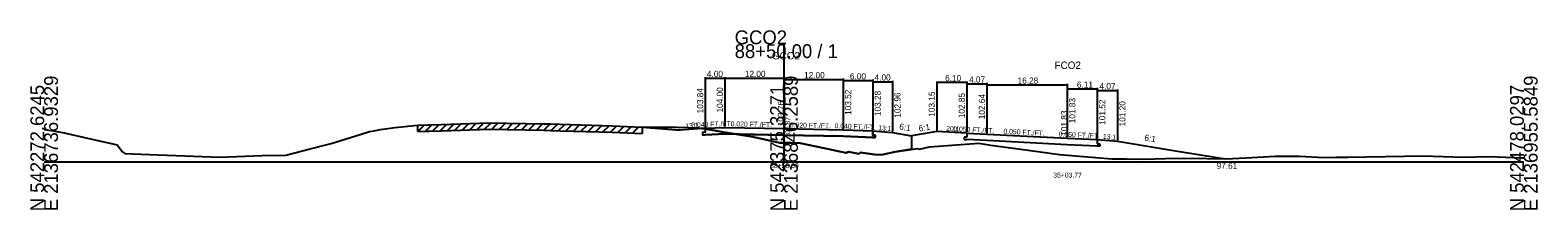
# Model space of a CAD drawing. Extents: x -14327 to 8886, y -10 to 39048.
# Drawn here: x 2997.2 to 3302.8, y 36990.3 to 37026.7 of the extents above; entities that cross this region are included whole.
import ezdxf

# ---------------------------------------------------------------- set-up
doc = ezdxf.new("R2010")
doc.units = 0
for name, color, linetype in [('Level 20', 7, 'Continuous'), ('Level 5', 7, 'Continuous'), ('Level 53', 7, 'Continuous'), ('Level 54', 7, 'Continuous'), ('Level 55', 7, 'Continuous'), ('Level 7', 7, 'Continuous'), ('RD_GPK_XS_Cell', 7, 'Continuous'), ('RD_XS_EwShp', 7, 'Continuous'), ('RD_XS_ExGround', 7, 'Continuous'), ('RD_XS_ExPaveRet', 7, 'Continuous'), ('RD_XS_Pave', 7, 'Continuous'), ('RD_XS_TX_Baseline', 7, 'Continuous'), ('RD_XS_TX_Elev_EX', 7, 'Continuous'), ('RD_XS_TX_Elev_PR', 7, 'Continuous'), ('RD_XS_TX_Station', 7, 'Continuous')]:
    doc.layers.add(name, color=color, linetype=linetype)

msp = doc.modelspace()

# ---------------------------------------------------------------- linework, layer by layer
at = {"layer": 'Level 20'}
for p, q in [((3180.96, 37016.3), (3180.96, 37006.35)), ((3187.06, 37016.1), (3180.96, 37016.1)), ((3187.06, 37016.3), (3187.06, 37006.05)), ((3187.06, 37016), (3187.06, 37006.05)), ((3187.06, 37015.8), (3191.13, 37015.8)), ((3191.13, 37016), (3191.13, 37005.84)), ((3191.13, 37015.79), (3191.13, 37005.84)), ((3191.13, 37015.59), (3207.41, 37015.59)), ((3207.41, 37015.79), (3207.41, 37005.03)), ((3207.41, 37014.98), (3207.41, 37005.03)), ((3213.52, 37014.98), (3213.52, 37004.72)), ((3207.41, 37014.78), (3213.52, 37014.78)), ((3213.52, 37014.67), (3213.52, 37004.72)), ((3213.52, 37014.47), (3217.59, 37014.47)), ((3217.59, 37014.67), (3217.59, 37004.4)), ((3180.96, 37006.15), (3175.88, 37005.31)), ((3187.06, 37005.85), (3180.96, 37006.15)), ((3187.06, 37005.85), (3187.06, 37005.01)), ((3187.06, 37005.85), (3191.13, 37005.64)), ((3186.56, 37005.04), (3186.56, 37004.54)), ((3187.06, 37005.01), (3186.56, 37005.04)), ((3186.56, 37004.54), (3187.06, 37004.51)), ((3191.13, 37004.31), (3187.06, 37004.51)), ((3191.13, 37005.64), (3207.41, 37004.83)), ((3207.41, 37003.49), (3191.13, 37004.31)), ((3207.41, 37004.83), (3213.52, 37004.52)), ((3213.52, 37003.19), (3207.41, 37003.49)), ((3213.52, 37004.52), (3213.52, 37003.69)), ((3213.52, 37004.52), (3217.59, 37004.2)), ((3213.52, 37003.69), (3214.03, 37003.66)), ((3214.03, 37003.16), (3213.52, 37003.19)), ((3214.03, 37003.66), (3214.03, 37003.16)), ((3217.59, 37004.2), (3229.8, 37002.2)), ((3229.8, 37002.2), (3239.52, 37000.61))]:
    msp.add_line(p, q, dxfattribs=at)
at = {"layer": 'Level 5'}
for p, q in [((3134, 37006.01), (3133.5, 37005.99)), ((3133.5, 37005.99), (3133.5, 37005.49)), ((3134, 37006.84), (3134, 37006.01)), ((3168, 37006.28), (3168, 37005.45)), ((3133.5, 37005.49), (3134, 37005.51)), ((3138, 37005.67), (3134, 37005.51)), ((3150, 37005.43), (3138, 37005.67)), ((3162, 37005.19), (3150, 37005.43)), ((3168, 37004.95), (3162, 37005.19)), ((3168, 37005.45), (3168.5, 37005.43)), ((3168.5, 37004.93), (3168, 37004.95)), ((3168.5, 37005.43), (3168.5, 37004.93))]:
    msp.add_line(p, q, dxfattribs=at)
at = {"layer": 'Level 54'}
for p, q in [((3134, 37017.15), (3134, 37007.04)), ((3134, 37016.99), (3134, 37007.04)), ((3134, 37016.95), (3138, 37016.95)), ((3138, 37017.15), (3138, 37007.2)), ((3138, 37016.95), (3150, 37016.95)), ((3150, 37017.15), (3150, 37006.96)), ((3150, 37016.91), (3150, 37006.96)), ((3150, 37016.71), (3162, 37016.71)), ((3162, 37016.91), (3162, 37006.72)), ((3162, 37016.67), (3162, 37006.72)), ((3162, 37016.47), (3168, 37016.47)), ((3168, 37016.67), (3168, 37006.48)), ((3168, 37016.43), (3168, 37006.48)), ((3168, 37016.23), (3172, 37016.23)), ((3172, 37016.43), (3172, 37006.16))]:
    msp.add_line(p, q, dxfattribs=at)
at = {"layer": 'Level 7'}
for p, q in [((3121.23, 37007.06), (3128.98, 37006.44)), ((3134, 37006.84), (3128.98, 37006.44)), ((3168, 37006.28), (3172, 37005.96)), ((3172, 37005.96), (3175.88, 37005.31)), ((3175.88, 37005.31), (3175.88, 37002.56))]:
    msp.add_line(p, q, dxfattribs=at)
at = {"layer": 'RD_GPK_XS_Cell'}
for p, q in [((3150, 37000), (3150, 37023.83)), ((3000, 37000), (3150, 37000)), ((3150, 37000), (3300, 37000))]:
    msp.add_line(p, q, dxfattribs=at)
at = {"layer": 'RD_XS_EwShp'}
for points in [[(3130.54, 37006.97), (3133.25, 37006.81), (3133.39, 37006.79), (3128.98, 37006.44), (3121.23, 37007.06), (3126.19, 37007.12)], [(3133.39, 37006.79), (3134, 37006.69), (3134, 37006.84)], [(3134, 37006.69), (3134, 37006.01), (3133.5, 37005.99), (3133.5, 37005.49), (3134, 37005.51), (3138, 37005.67), (3140.36, 37005.62), (3138.12, 37005.98)], [(3175.88, 37005.31), (3175.88, 37002.56), (3172.56, 37002.07), (3169.77, 37001.47), (3168.38, 37001.5), (3165.49, 37001.91), (3165.15, 37001.64), (3163.12, 37002.03), (3162.52, 37001.82), (3157.79, 37002.84), (3153.26, 37003.79), (3151.33, 37003.86), (3150, 37003.87), (3149.12, 37003.88), (3146.1, 37004.54), (3143.26, 37005.15), (3140.36, 37005.62), (3150, 37005.43), (3162, 37005.19), (3168, 37004.95), (3168.5, 37004.93), (3168.5, 37005.43), (3168, 37005.45), (3168, 37006.28), (3172, 37005.96)]]:
    msp.add_lwpolyline(points, close=True, dxfattribs=at)
at = {"layer": 'RD_XS_ExGround'}
for p, q in [((3000, 37006.54), (3001.82, 37006.33)), ((3001.82, 37006.33), (3004.04, 37005.92)), ((3004.04, 37005.92), (3010.3, 37004.5)), ((3063.18, 37005.28), (3065.99, 37006.14)), ((3065.99, 37006.14), (3066.82, 37006.29)), ((3066.82, 37006.29), (3068.18, 37006.59)), ((3068.18, 37006.59), (3071.11, 37006.98)), ((3071.11, 37006.98), (3075.76, 37007.45)), ((3075.76, 37007.45), (3077.77, 37007.51)), ((3077.77, 37007.51), (3078.08, 37007.52)), ((3078.08, 37007.52), (3080.51, 37007.6)), ((3080.51, 37007.6), (3090.22, 37007.94)), ((3090.22, 37007.94), (3101.27, 37007.72)), ((3101.27, 37007.72), (3102.64, 37007.69)), ((3102.64, 37007.69), (3104.64, 37007.63)), ((3104.64, 37007.63), (3115.19, 37007.31)), ((3115.19, 37007.31), (3121.23, 37007.06)), ((3121.23, 37007.06), (3126.19, 37007.12)), ((3126.19, 37007.12), (3130.54, 37006.97)), ((3130.54, 37006.97), (3133.25, 37006.81)), ((3133.25, 37006.81), (3138.12, 37005.98)), ((3138.12, 37005.98), (3143.26, 37005.15)), ((3010.3, 37004.5), (3014.83, 37003.45)), ((3014.83, 37003.45), (3015.85, 37002.04)), ((3053.68, 37002.59), (3058.16, 37003.74)), ((3058.16, 37003.74), (3063.18, 37005.28)), ((3143.26, 37005.15), (3146.1, 37004.54)), ((3146.1, 37004.54), (3149.12, 37003.88)), ((3149.12, 37003.88), (3150, 37003.87)), ((3150, 37003.87), (3151.33, 37003.86)), ((3151.33, 37003.86), (3153.26, 37003.79)), ((3153.26, 37003.79), (3157.79, 37002.84)), ((3157.79, 37002.84), (3162.52, 37001.82)), ((3172.56, 37002.07), (3177.15, 37002.75)), ((3177.15, 37002.75), (3177.49, 37002.57)), ((3177.49, 37002.57), (3179.47, 37003.07)), ((3179.47, 37003.07), (3181.35, 37003.21)), ((3181.35, 37003.21), (3189.48, 37003.82)), ((3189.48, 37003.82), (3191.95, 37003.42)), ((3191.95, 37003.42), (3199.49, 37002.4)), ((3015.85, 37002.04), (3016.34, 37001.71)), ((3016.34, 37001.71), (3019.63, 37001.57)), ((3019.63, 37001.57), (3035.59, 37000.95)), ((3035.59, 37000.95), (3044.2, 37001.31)), ((3044.2, 37001.31), (3049.03, 37001.38)), ((3049.03, 37001.38), (3053.68, 37002.59)), ((3162.52, 37001.82), (3163.12, 37002.03)), ((3163.12, 37002.03), (3165.15, 37001.64)), ((3165.15, 37001.64), (3165.49, 37001.91)), ((3165.49, 37001.91), (3168.38, 37001.5)), ((3168.38, 37001.5), (3169.77, 37001.47)), ((3169.77, 37001.47), (3172.56, 37002.07)), ((3199.49, 37002.4), (3205.83, 37001.48)), ((3205.83, 37001.48), (3216.44, 37000.62)), ((3216.44, 37000.62), (3219.51, 37000.64)), ((3219.51, 37000.64), (3222.97, 37000.56)), ((3222.97, 37000.56), (3229.52, 37000.76)), ((3229.52, 37000.76), (3235.81, 37000.71)), ((3235.81, 37000.71), (3239.53, 37000.61)), ((3239.53, 37000.61), (3243.67, 37000.8)), ((3243.67, 37000.8), (3249.54, 37001.14)), ((3249.54, 37001.14), (3254.43, 37001.17)), ((3254.43, 37001.17), (3259.55, 37000.91)), ((3259.55, 37000.91), (3262.01, 37000.96)), ((3262.01, 37000.96), (3264.4, 37000.99)), ((3264.4, 37000.99), (3279.57, 37001.25)), ((3279.57, 37001.25), (3287.77, 37000.96)), ((3287.77, 37000.96), (3292.98, 37001.08)), ((3292.98, 37001.08), (3299.58, 37000.86)), ((3299.58, 37000.86), (3300, 37000.85))]:
    msp.add_line(p, q, dxfattribs=at)
at = {"layer": 'RD_XS_ExPaveRet'}
for p, q in [((3075.76, 37006.15), (3077.1, 37007.49)), ((3075.76, 37006.15), (3075.76, 37007.45)), ((3075.76, 37006.15), (3077.77, 37006.21)), ((3077.26, 37006.19), (3078.61, 37007.54)), ((3077.77, 37006.21), (3078.08, 37006.22)), ((3078.08, 37006.22), (3080.51, 37006.3)), ((3078.76, 37006.24), (3080.11, 37007.59)), ((3080.26, 37006.29), (3081.61, 37007.64)), ((3080.51, 37006.3), (3090.22, 37006.64)), ((3081.77, 37006.35), (3083.11, 37007.69)), ((3083.27, 37006.4), (3084.62, 37007.75)), ((3084.77, 37006.45), (3086.12, 37007.8)), ((3086.27, 37006.51), (3087.62, 37007.85)), ((3087.77, 37006.56), (3089.12, 37007.91)), ((3089.27, 37006.61), (3090.6, 37007.94)), ((3090.22, 37006.64), (3101.27, 37006.42)), ((3090.78, 37006.63), (3092.05, 37007.91)), ((3092.28, 37006.6), (3093.55, 37007.88)), ((3093.78, 37006.57), (3095.05, 37007.84)), ((3095.28, 37006.54), (3096.56, 37007.81)), ((3096.78, 37006.51), (3098.06, 37007.78)), ((3098.29, 37006.48), (3099.56, 37007.75)), ((3099.79, 37006.45), (3101.06, 37007.72)), ((3101.27, 37006.42), (3102.64, 37006.39)), ((3101.29, 37006.41), (3102.57, 37007.69)), ((3102.64, 37006.39), (3104.64, 37006.33)), ((3102.79, 37006.38), (3104.05, 37007.64)), ((3104.29, 37006.34), (3105.56, 37007.6)), ((3104.64, 37006.33), (3115.19, 37006.01)), ((3105.79, 37006.29), (3107.06, 37007.55)), ((3107.3, 37006.25), (3108.56, 37007.51)), ((3108.8, 37006.2), (3110.06, 37007.46)), ((3110.3, 37006.16), (3111.56, 37007.42)), ((3111.8, 37006.11), (3113.07, 37007.37)), ((3113.3, 37006.07), (3114.57, 37007.33)), ((3114.81, 37006.02), (3116.06, 37007.27)), ((3115.19, 37006.01), (3121.23, 37005.76)), ((3116.31, 37005.96), (3117.56, 37007.21)), ((3117.81, 37005.9), (3119.06, 37007.15)), ((3119.31, 37005.84), (3120.56, 37007.09)), ((3121.23, 37007.06), (3121.23, 37005.76))]:
    msp.add_line(p, q, dxfattribs=at)
at = {"layer": 'RD_XS_Pave'}
for p, q in [((3134, 37006.84), (3138, 37007)), ((3138, 37007), (3150, 37006.76)), ((3150, 37006.76), (3162, 37006.52)), ((3162, 37006.52), (3168, 37006.28))]:
    msp.add_line(p, q, dxfattribs=at)

# ---------------------------------------------------------------- texts
at = {"layer": 'Level 20'}
for s, height, p in [('FCO2', 1.5, (3204.84, 37018.83)), ('6.10', 1.25, (3182.66, 37016.35)), ('4.07', 1.25, (3187.52, 37016.05)), ('16.28', 1.25, (3197.36, 37015.84)), ('6.11', 1.25, (3209.39, 37015.03)), ('4.07', 1.25, (3213.97, 37014.72)), ('97.61', 1.25, (3237.71, 36998.61)), ('35+03.77', 1, (3204.59, 36996.83))]:
    msp.add_text(s, height=height, dxfattribs=at).set_placement(p)
for s, height, rotation, p in [('103.15', 1.25, 90, (3180.57, 37009.15)), ('102.85', 1.25, 90, (3186.67, 37008.85)), ('102.64', 1.25, 90, (3190.74, 37008.64)), ('101.83', 1.25, 90, (3209.06, 37007.83)), ('101.52', 1.25, 90, (3215.16, 37007.52)), ('101.20', 1.25, 90, (3219.23, 37007.2)), (' 101.83', 1.25, 90, (3207.41, 37004.83)), ('6:1', 1.25, 9.3052, (3177.4, 37006.13)), ('20:1', 1, 357.1846, (3182.86, 37006.3)), ('0.050 FT./FT.', 1, 357.1362, (3184.31, 37006.23)), ('0.050 FT./FT.', 1, 357.1362, (3194.48, 37005.73)), ('0.050 FT./FT.', 1, 357.1362, (3205.68, 37005.17)), ('13:1', 1, 355.5055, (3214.62, 37004.69)), ('6:1', 1.25, 350.6997, (3222.99, 37004.33))]:
    msp.add_text(s, height=height, rotation=rotation, dxfattribs=at).set_placement(p)
at = {"layer": 'Level 53'}
for s, rotation, p in [('104.00', 90, (3137.62, 37010)), ('103.84', 90, (3133.62, 37009.84)), ('103.52', 90, (3163.62, 37009.52)), ('103.28', 90, (3169.62, 37009.28)), ('102.96', 90, (3173.62, 37008.96)), ('6:1', 350.5377, (3173.29, 37006.61))]:
    msp.add_text(s, height=1.25, rotation=rotation, dxfattribs=at).set_placement(p)
at = {"layer": 'Level 54'}
for s, p in [('4.00', (3134.37, 37017.2)), ('12.00', (3142.07, 37017.2)), ('12.00', (3154.07, 37016.96)), ('6.00', (3163.37, 37016.72)), ('4.00', (3168.37, 37016.48))]:
    msp.add_text(s, height=1.25, dxfattribs=at).set_placement(p)
at = {"layer": 'Level 55'}
for s, rotation, p in [('13:1', 4.5739, (3130.03, 37006.77)), ('0.040 FT./FT.', 2.2906, (3131.22, 37006.98)), ('0.020 FT./FT.', 358.8542, (3139.18, 37007.23)), ('0.020 FT./FT.', 358.8542, (3151.18, 37006.99)), ('0.040 FT./FT.', 357.7094, (3160.24, 37006.84)), ('13:1', 355.4261, (3169.07, 37006.45))]:
    msp.add_text(s, height=1, rotation=rotation, dxfattribs=at).set_placement(p)
at = {"layer": 'RD_GPK_XS_Cell'}
for s, p in [('GCO2', (3140, 37023.83)), ('88+50.00 / 1', (3140, 37021.03))]:
    msp.add_text(s, height=2.8, dxfattribs=at).set_placement(p)
for s, p in [('N 542272.6245', (3000, 36990)), ('E 2136736.9329', (3002.8, 36990)), ('N 542375.3271', (3150, 36990)), ('E 2136846.2589', (3152.8, 36990)), ('N 542478.0297', (3300, 36990)), ('E 2136955.5849', (3302.8, 36990))]:
    msp.add_text(s, height=2.8, rotation=90, dxfattribs=at).set_placement(p)
at = {"layer": 'RD_XS_TX_Baseline'}
msp.add_text('GCO2', height=1.5, dxfattribs=at).set_placement((3147.55, 37020.76))
at = {"layer": 'RD_XS_TX_Elev_EX'}
msp.add_text('100.87', height=1, rotation=90, dxfattribs=at).set_placement((3151.25, 37004.87))
at = {"layer": 'RD_XS_TX_Elev_PR'}
msp.add_text(' 103.76', height=1.25, rotation=90, dxfattribs=at).set_placement((3150, 37006.76))
at = {"layer": 'RD_XS_TX_Station'}
msp.add_text('88+50.00', height=1, dxfattribs=at).set_placement((3147.18, 36998.76))

doc.saveas('drawing.dxf')
